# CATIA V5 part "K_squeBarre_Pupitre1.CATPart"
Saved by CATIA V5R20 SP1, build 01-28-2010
Part number: squelette_barre_pupitre_1
Publications: "Point.1", "Point.2", "Plan.1", "Droite.1", "Droite.2", "Droite.3"
Bounding box of the stored display mesh (mm): x 0 to 20, y 0 to 0, z 0 to 200
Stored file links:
  G:\Khaled_CFAO_2011\ST2M\ST2M_GR2\gcausse\Khaled\CAD_ThinkMotion\K_squeBarre_Pupitre1.CATPart
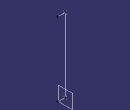
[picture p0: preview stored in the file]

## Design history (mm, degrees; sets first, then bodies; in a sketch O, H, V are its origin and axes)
Set1
  Point1: (0, 0, 0)
  Point2: (0, 0, 200)
  Plane1: type Offset, RefPlane yz-plane, Offset 0
  Line1: type PtPt, FirstPoint Point2, SecondPoint Point1
  Line2: type PtDir, RefPoint Point2, Direction Plane1, Start 0, End 20
  Line3: type PtDir, RefPoint Point1, Direction Plane1, Start 0, End 20
Body1 (main body)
